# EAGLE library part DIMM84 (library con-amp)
AMP connector
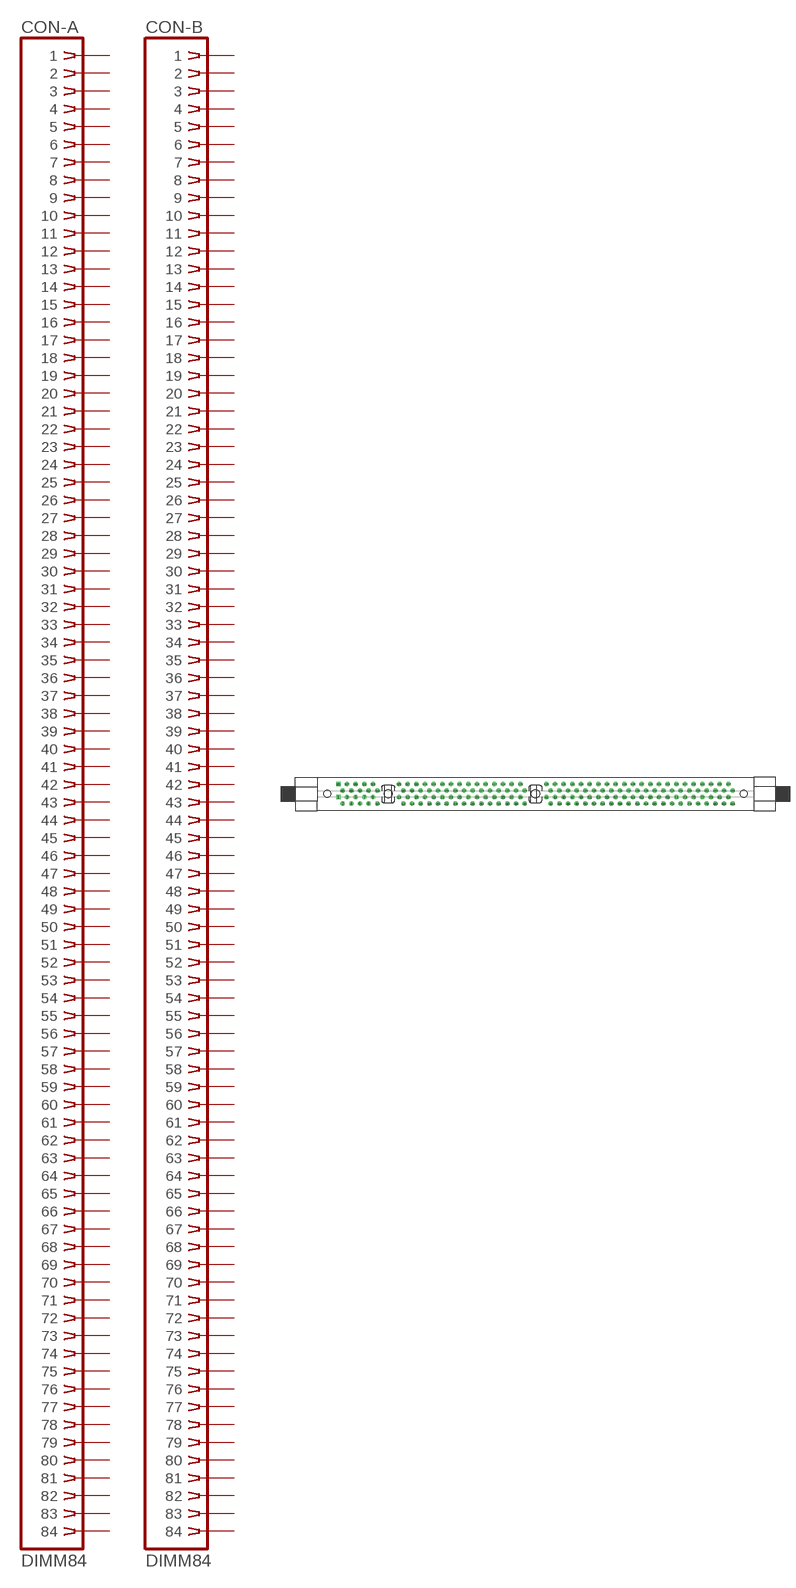
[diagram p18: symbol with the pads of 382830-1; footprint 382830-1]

Designator prefix CON; gates -A=SIMM84 -B=SIMM84

## DIMM84 (OC_FARNELL: unknown; OC_NEWARK: unknown)  [382830-1]
1  -A:1  pas
2  -A:2  pas
3  -A:3  pas
4  -A:4  pas
5  -A:5  pas
6  -A:6  pas
7  -A:7  pas
8  -A:8  pas
9  -A:9  pas
10  -A:10  pas
11  -A:11  pas
12  -A:12  pas
13  -A:13  pas
14  -A:14  pas
15  -A:15  pas
16  -A:16  pas
17  -A:17  pas
18  -A:18  pas
19  -A:19  pas
20  -A:20  pas
21  -A:21  pas
22  -A:22  pas
23  -A:23  pas
24  -A:24  pas
25  -A:25  pas
26  -A:26  pas
27  -A:27  pas
28  -A:28  pas
29  -A:29  pas
30  -A:30  pas
31  -A:31  pas
32  -A:32  pas
33  -A:33  pas
34  -A:34  pas
35  -A:35  pas
36  -A:36  pas
37  -A:37  pas
38  -A:38  pas
39  -A:39  pas
40  -A:40  pas
41  -A:41  pas
42  -A:42  pas
43  -A:43  pas
44  -A:44  pas
45  -A:45  pas
46  -A:46  pas
47  -A:47  pas
48  -A:48  pas
49  -A:49  pas
50  -A:50  pas
51  -A:51  pas
52  -A:52  pas
53  -A:53  pas
54  -A:54  pas
55  -A:55  pas
56  -A:56  pas
57  -A:57  pas
58  -A:58  pas
59  -A:59  pas
60  -A:60  pas
61  -A:61  pas
62  -A:62  pas
63  -A:63  pas
64  -A:64  pas
65  -A:65  pas
66  -A:66  pas
67  -A:67  pas
68  -A:68  pas
69  -A:69  pas
70  -A:70  pas
71  -A:71  pas
72  -A:72  pas
73  -A:73  pas
74  -A:74  pas
75  -A:75  pas
76  -A:76  pas
77  -A:77  pas
78  -A:78  pas
79  -A:79  pas
80  -A:80  pas
81  -A:81  pas
82  -A:82  pas
83  -A:83  pas
84  -A:84  pas
85  -B:1  pas
86  -B:2  pas
87  -B:3  pas
88  -B:4  pas
89  -B:5  pas
90  -B:6  pas
91  -B:7  pas
92  -B:8  pas
93  -B:9  pas
94  -B:10  pas
95  -B:11  pas
96  -B:12  pas
97  -B:13  pas
98  -B:14  pas
99  -B:15  pas
100  -B:16  pas
101  -B:17  pas
102  -B:18  pas
103  -B:19  pas
104  -B:20  pas
105  -B:21  pas
106  -B:22  pas
107  -B:23  pas
108  -B:24  pas
109  -B:25  pas
110  -B:26  pas
111  -B:27  pas
112  -B:28  pas
113  -B:29  pas
114  -B:30  pas
115  -B:31  pas
116  -B:32  pas
117  -B:33  pas
118  -B:34  pas
119  -B:35  pas
120  -B:36  pas
121  -B:37  pas
122  -B:38  pas
123  -B:39  pas
124  -B:40  pas
125  -B:41  pas
126  -B:42  pas
127  -B:43  pas
128  -B:44  pas
129  -B:45  pas
130  -B:46  pas
131  -B:47  pas
132  -B:48  pas
133  -B:49  pas
134  -B:50  pas
135  -B:51  pas
136  -B:52  pas
137  -B:53  pas
138  -B:54  pas
139  -B:55  pas
140  -B:56  pas
141  -B:57  pas
142  -B:58  pas
143  -B:59  pas
144  -B:60  pas
145  -B:61  pas
146  -B:62  pas
147  -B:63  pas
148  -B:64  pas
149  -B:65  pas
150  -B:66  pas
151  -B:67  pas
152  -B:68  pas
153  -B:69  pas
154  -B:70  pas
155  -B:71  pas
156  -B:72  pas
157  -B:73  pas
158  -B:74  pas
159  -B:75  pas
160  -B:76  pas
161  -B:77  pas
162  -B:78  pas
163  -B:79  pas
164  -B:80  pas
165  -B:81  pas
166  -B:82  pas
167  -B:83  pas
168  -B:84  pas

## Footprint 382830-1 (pad centres in mm)
Std. DRAM 5 Volt
drill 0.813 square: 1 -57.785,-0.953; 85 -57.785,2.857
drill 0.813 octagon: 2 -56.515,-2.857; 3 -55.245,-0.953; 4 -53.975,-2.857; 5 -52.705,-0.953; 6 -51.435,-2.857; 7 -50.165,-0.953; 8 -48.895,-2.857; 9 -47.625,-0.953; 10 -46.355,-2.857; 11 -40.005,-0.953; 12 -38.735,-2.857; 13 -37.465,-0.953; 14 -36.195,-2.857; 15 -34.925,-0.953; 16 -33.655,-2.857; 17 -32.385,-0.953; 18 -31.115,-2.857; 19 -29.845,-0.953; 20 -28.575,-2.857; 21 -27.305,-0.953; 22 -26.035,-2.857; 23 -24.765,-0.953; 24 -23.495,-2.857; 25 -22.225,-0.953; 26 -20.955,-2.857; 27 -19.685,-0.953; 28 -18.415,-2.857; 29 -17.145,-0.953; 30 -15.875,-2.857; 31 -14.605,-0.953; 32 -13.335,-2.857; 33 -12.065,-0.953; 34 -10.795,-2.857; 35 -9.525,-0.953; 36 -8.255,-2.857; 37 -6.985,-0.953; 38 -5.715,-2.857; 39 -4.445,-0.953; 40 -3.175,-2.857; 41 3.175,-0.953; 42 4.445,-2.857; 43 5.715,-0.953; 44 6.985,-2.857; 45 8.255,-0.953; 46 9.525,-2.857; 47 10.795,-0.953; 48 12.065,-2.857; 49 13.335,-0.953; 50 14.605,-2.857; 51 15.875,-0.953; 52 17.145,-2.857; 53 18.415,-0.953; 54 19.685,-2.857; 55 20.955,-0.953; 56 22.225,-2.857; 57 23.495,-0.953; 58 24.765,-2.857; 59 26.035,-0.953; 60 27.305,-2.857; 61 28.575,-0.953; 62 29.845,-2.857; 63 31.115,-0.953; 64 32.385,-2.857; 65 33.655,-0.953; 66 34.925,-2.857; 67 36.195,-0.953; 68 37.465,-2.857; 69 38.735,-0.953; 70 40.005,-2.857; 71 41.275,-0.953; 72 42.545,-2.857; 73 43.815,-0.953; 74 45.085,-2.857; 75 46.355,-0.953; 76 47.625,-2.857; 77 48.895,-0.953; 78 50.165,-2.857; 79 51.435,-0.953; 80 52.705,-2.857; 81 53.975,-0.953; 82 55.245,-2.857; 83 56.515,-0.953; 84 57.785,-2.857; 86 -56.515,0.953; 87 -55.245,2.857; 88 -53.975,0.953; 89 -52.705,2.857; 90 -51.435,0.953; 91 -50.165,2.857; 92 -48.895,0.953; 93 -47.625,2.857; 94 -46.355,0.953; 95 -40.005,2.857; 96 -38.735,0.953; 97 -37.465,2.857; 98 -36.195,0.953; 99 -34.925,2.857; 100 -33.655,0.953; 101 -32.385,2.857; 102 -31.115,0.953; 103 -29.845,2.857; 104 -28.575,0.953; 105 -27.305,2.857; 106 -26.035,0.953; 107 -24.765,2.857; 108 -23.495,0.953; 109 -22.225,2.857; 110 -20.955,0.953; 111 -19.685,2.857; 112 -18.415,0.953; 113 -17.145,2.857; 114 -15.875,0.953; 115 -14.605,2.857; 116 -13.335,0.953; 117 -12.065,2.857; 118 -10.795,0.953; 119 -9.525,2.857; 120 -8.255,0.953; 121 -6.985,2.857; 122 -5.715,0.953; 123 -4.445,2.857; 124 -3.175,0.953; 125 3.175,2.857; 126 4.445,0.953; 127 5.715,2.857; 128 6.985,0.953; 129 8.255,2.857; 130 9.525,0.953; 131 10.795,2.857; 132 12.065,0.953; 133 13.335,2.857; 134 14.605,0.953; 135 15.875,2.857; 136 17.145,0.953; 137 18.415,2.857; 138 19.685,0.953; 139 20.955,2.857; 140 22.225,0.953; 141 23.495,2.857; 142 24.765,0.953; 143 26.035,2.857; 144 27.305,0.953; 145 28.575,2.857; 146 29.845,0.953; 147 31.115,2.857; 148 32.385,0.953; 149 33.655,2.857; 150 34.925,0.953; 151 36.195,2.857; 152 37.465,0.953; 153 38.735,2.857; 154 40.005,0.953; 155 41.275,2.857; 156 42.545,0.953; 157 43.815,2.857; 158 45.085,0.953; 159 46.355,2.857; 160 47.625,0.953; 161 48.895,2.857; 162 50.165,0.953; 163 51.435,2.857; 164 52.705,0.953; 165 53.975,2.857; 166 55.245,0.953; 167 56.515,2.857; 168 57.785,0.953
hole 2.032 at -60.96,0
hole 2.032 at 60.96,0
hole 2.362 at 0,0
hole 2.362 at -43.18,0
